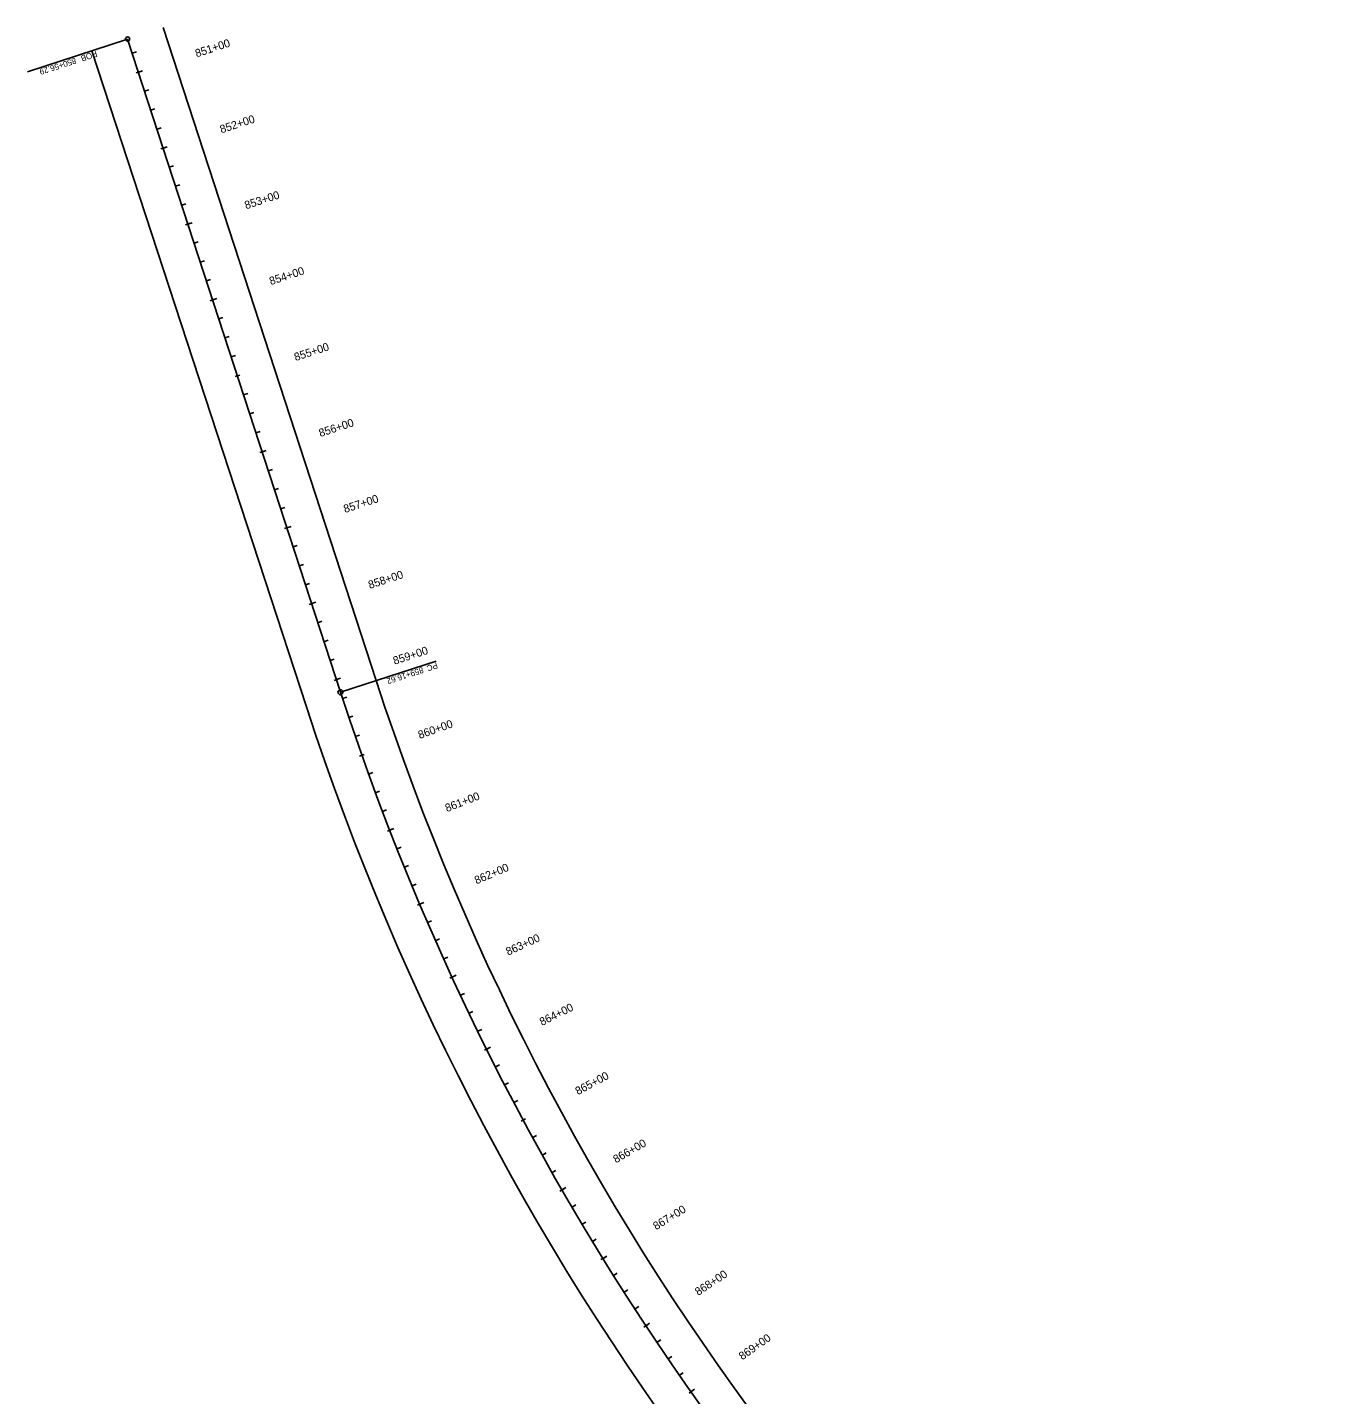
# Model space of a CAD drawing. Extents: x 14448949 to 14455476, y 8570587 to 8573998.
# Drawn here: x 14448949 to 14450580, y 8572286 to 8573998 of the extents above; entities that cross this region are included whole.
import ezdxf

# ---------------------------------------------------------------- set-up
doc = ezdxf.new("R2010")
doc.units = 0
for name, color, linetype in [('Alignment', 7, 'Continuous'), ('TextAlignment', 7, 'Continuous'), ('TextAlignmentLrg', 7, 'Continuous'), ('TextAlignmentSml', 7, 'Continuous'), ('TextNonPlot', 7, 'Continuous')]:
    doc.layers.add(name, color=color, linetype=linetype)

msp = doc.modelspace()

# ---------------------------------------------------------------- linework, layer by layer
at = {"layer": 'Alignment'}
msp.add_line((14449074.9, 8573983.8), (14449341.4, 8573165.8), dxfattribs=at)
msp.add_line((14449074.9, 8573983.8), (14449341.4, 8573165.8), dxfattribs=at)
msp.add_arc((14452465.5, 8574183.5), 3285.7, 198.0445, 274.688, dxfattribs=at)
msp.add_arc((14452465.5, 8574183.5), 3285.7, 198.0445, 274.688, dxfattribs=at)
at = {"layer": 'TextAlignment'}
for p, q in [((14449074.9, 8573983.8), (14448949.4, 8573942.9)), ((14448949.4, 8573942.9), (14448949.4, 8573942.9)), ((14449341.4, 8573165.8), (14449461.2, 8573204.8)), ((14449461.2, 8573204.8), (14449461.2, 8573204.8))]:
    msp.add_line(p, q, dxfattribs=at)
for centre, radius in [((14449074.9, 8573983.8), 2.67), ((14449341.4, 8573165.8), 3.12)]:
    msp.add_circle(centre, radius, dxfattribs=at)
at = {"layer": 'TextAlignmentLrg'}
for p, q in [((14449088.4, 8573942.2), (14449093.6, 8573943.9)), ((14449119.4, 8573847.2), (14449124.6, 8573848.9)), ((14449150.4, 8573752.1), (14449155.6, 8573753.8)), ((14449181.3, 8573657), (14449186.5, 8573658.7)), ((14449215.2, 8573562.9), (14449209.4, 8573561)), ((14449243.3, 8573466.8), (14449248.5, 8573468.5)), ((14449274.3, 8573371.8), (14449279.5, 8573373.4)), ((14449305.2, 8573276.7), (14449310.4, 8573278.4)), ((14449336.2, 8573181.6), (14449341.4, 8573183.3)), ((14449371.1, 8573087.9), (14449365.3, 8573085.8)), ((14449403, 8572993.1), (14449408.1, 8572995.1)), ((14449440.7, 8572900.5), (14449445.7, 8572902.6)), ((14449481.1, 8572809), (14449486.1, 8572811.3)), ((14449524.3, 8572718.8), (14449529.2, 8572721.3)), ((14449572.9, 8572631.5), (14449567.5, 8572628.6)), ((14449618.9, 8572542.6), (14449623.6, 8572545.4)), ((14449670.1, 8572456.8), (14449674.8, 8572459.6)), ((14449724, 8572372.5), (14449728.5, 8572375.5)), ((14449780.3, 8572289.9), (14449784.8, 8572293.1))]:
    msp.add_line(p, q, dxfattribs=at)
at = {"layer": 'TextAlignmentSml'}
for p, q in [((14449080.7, 8573966), (14449085.9, 8573967.7)), ((14449091.3, 8573943.2), (14449085.5, 8573941.3)), ((14449096.2, 8573918.5), (14449101.4, 8573920.2)), ((14449103.9, 8573894.7), (14449109.1, 8573896.4)), ((14449111.7, 8573870.9), (14449116.8, 8573872.6)), ((14449122.3, 8573848.1), (14449116.5, 8573846.2)), ((14449127.1, 8573823.4), (14449132.3, 8573825.1)), ((14449134.9, 8573799.6), (14449140.1, 8573801.3)), ((14449142.6, 8573775.8), (14449147.8, 8573777.5)), ((14449153.3, 8573753), (14449147.5, 8573751.1)), ((14449158.1, 8573728.3), (14449163.3, 8573730)), ((14449165.9, 8573704.5), (14449171.1, 8573706.2)), ((14449173.6, 8573680.8), (14449178.8, 8573682.5)), ((14449184.3, 8573657.9), (14449178.4, 8573656)), ((14449189.1, 8573633.2), (14449194.3, 8573634.9)), ((14449196.8, 8573609.5), (14449202, 8573611.1)), ((14449204.6, 8573585.7), (14449209.8, 8573587.4)), ((14449215.2, 8573562.9), (14449209.4, 8573561)), ((14449220.1, 8573538.1), (14449225.3, 8573539.8)), ((14449227.8, 8573514.4), (14449233, 8573516.1)), ((14449235.6, 8573490.6), (14449240.7, 8573492.3)), ((14449246.2, 8573467.8), (14449240.4, 8573465.9)), ((14449251, 8573443.1), (14449256.2, 8573444.8)), ((14449258.8, 8573419.3), (14449264, 8573421)), ((14449266.5, 8573395.5), (14449271.7, 8573397.2)), ((14449277.2, 8573372.7), (14449271.4, 8573370.8)), ((14449282, 8573348), (14449287.2, 8573349.7)), ((14449289.8, 8573324.2), (14449295, 8573325.9)), ((14449297.5, 8573300.4), (14449302.7, 8573302.1)), ((14449308.2, 8573277.6), (14449302.3, 8573275.7)), ((14449313, 8573252.9), (14449318.2, 8573254.6)), ((14449320.7, 8573229.1), (14449325.9, 8573230.8)), ((14449328.5, 8573205.4), (14449333.7, 8573207.1)), ((14449339.1, 8573182.5), (14449333.3, 8573180.6)), ((14449344, 8573157.8), (14449349.2, 8573159.5)), ((14449351.9, 8573134.1), (14449357, 8573135.8)), ((14449359.9, 8573110.4), (14449365.1, 8573112.2)), ((14449371.1, 8573087.9), (14449365.3, 8573085.8)), ((14449376.6, 8573063.3), (14449381.8, 8573065.2)), ((14449385.3, 8573039.8), (14449390.4, 8573041.7)), ((14449394, 8573016.4), (14449399.1, 8573018.4)), ((14449405.9, 8572994.2), (14449400.2, 8572992)), ((14449412.2, 8572969.8), (14449417.2, 8572971.9)), ((14449421.5, 8572946.6), (14449426.5, 8572948.7)), ((14449431, 8572923.5), (14449436, 8572925.6)), ((14449443.5, 8572901.7), (14449437.8, 8572899.3)), ((14449450.5, 8572877.5), (14449455.5, 8572879.7)), ((14449460.5, 8572854.6), (14449465.5, 8572856.8)), ((14449470.7, 8572831.8), (14449475.7, 8572834)), ((14449483.9, 8572810.3), (14449478.3, 8572807.7)), ((14449491.6, 8572786.3), (14449496.6, 8572788.7)), ((14449502.4, 8572763.8), (14449507.3, 8572766.1)), ((14449513.3, 8572741.3), (14449518.2, 8572743.6)), ((14449527, 8572720.2), (14449521.6, 8572717.5)), ((14449535.5, 8572696.5), (14449540.4, 8572699)), ((14449546.9, 8572674.2), (14449551.8, 8572676.8)), ((14449558.5, 8572652.1), (14449563.3, 8572654.6)), ((14449572.9, 8572631.5), (14449567.5, 8572628.6)), ((14449582.1, 8572608), (14449586.9, 8572610.6)), ((14449594.2, 8572586.1), (14449599, 8572588.8)), ((14449606.5, 8572564.3), (14449611.2, 8572567)), ((14449621.5, 8572544.2), (14449616.2, 8572541.1)), ((14449631.4, 8572521), (14449636.1, 8572523.8)), ((14449644.2, 8572499.5), (14449648.8, 8572502.3)), ((14449657.1, 8572478.1), (14449661.7, 8572480.9)), ((14449672.7, 8572458.4), (14449667.5, 8572455.2)), ((14449683.3, 8572435.5), (14449688, 8572438.4)), ((14449696.7, 8572414.4), (14449701.3, 8572417.4)), ((14449710.3, 8572393.4), (14449714.8, 8572396.4)), ((14449726.5, 8572374.2), (14449721.4, 8572370.8)), ((14449737.8, 8572351.7), (14449742.3, 8572354.7)), ((14449751.8, 8572331), (14449756.3, 8572334.1)), ((14449766, 8572310.4), (14449770.5, 8572313.5)), ((14449782.8, 8572291.7), (14449777.8, 8572288.1))]:
    msp.add_line(p, q, dxfattribs=at)
at = {"layer": 'TextNonPlot'}
for p, q in [((14449119.5, 8573998.4), (14449385.9, 8573180.6)), ((14449030.2, 8573969.2), (14449298.7, 8573147.3))]:
    msp.add_line(p, q, dxfattribs=at)
for centre, radius, start, end in [((14452466.6, 8574184.2), 3240, 198.0445, 274.688), ((14452464.1, 8574181.3), 3330, 198.0899, 274.6933)]:
    msp.add_arc(centre, radius, start, end, dxfattribs=at)

# ---------------------------------------------------------------- texts
at = {"layer": 'TextAlignment'}
for s, p in [('POB ', (14449035.5, 8573969.2)), ('850+56.29', (14449009.1, 8573960.6)), ('859+16.62', (14449443.9, 8573197.5)), ('PC', (14449461.7, 8573203.2))]:
    msp.add_text(s, height=7.5, rotation=198.0445, dxfattribs=at).set_placement(p)
at = {"layer": 'TextAlignmentLrg'}
for s, rotation, p in [('855+00', 18.0445, (14449285.2, 8573580.4)), ('860+00', 19.4985, (14449440.6, 8573107.2)), ('865+00', 28.2175, (14449638.7, 8572661.1))]:
    msp.add_text(s, height=10.02, rotation=rotation, dxfattribs=at).set_placement(p)
at = {"layer": 'TextAlignmentSml'}
for s, rotation, p in [('851+00', 18.0445, (14449161.3, 8573960.7)), ('852+00', 18.0445, (14449192.3, 8573865.6)), ('853+00', 18.0445, (14449223.2, 8573770.5)), ('854+00', 18.0445, (14449254.2, 8573675.5)), ('855+00', 18.0445, (14449285.2, 8573580.4)), ('856+00', 18.0445, (14449316.2, 8573485.3)), ('857+00', 18.0445, (14449347.1, 8573390.2)), ('858+00', 18.0445, (14449378.1, 8573295.1)), ('859+00', 18.0445, (14449409.1, 8573200.1)), ('860+00', 19.4985, (14449440.6, 8573107.2)), ('861+00', 21.2423, (14449474.7, 8573015.6)), ('862+00', 22.9861, (14449511.7, 8572925.1)), ('863+00', 24.7299, (14449551.3, 8572835.8)), ('864+00', 26.4737, (14449593.7, 8572747.8)), ('865+00', 28.2175, (14449638.7, 8572661.1)), ('866+00', 29.9613, (14449686.3, 8572575.7)), ('867+00', 31.7051, (14449736.6, 8572491.9)), ('868+00', 33.4489, (14449789.3, 8572409.7)), ('869+00', 35.1927, (14449844.5, 8572329))]:
    msp.add_text(s, height=10.02, rotation=rotation, dxfattribs=at).set_placement(p)

doc.saveas('drawing.dxf')
